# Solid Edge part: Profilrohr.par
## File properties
Username: bmolnar
Dokumentum tartalom típus: 0
Author: bmolnar
Last saved by: bmolnar
Revision: 91
Sűrűség: 0,000 kg/m^3
Pontosság: 0,990
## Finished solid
Body 1: solid body, 115 faces, 338 edges, 224 vertices.
  Faces by surface: cylinder 59, plane 56
  Edges by curve: line 220, circle 118
Bounding box of the edges (mm): 95.500 x 95.500 x 184.000, from (-47.75, -47.75, -155) to (47.75, 47.75, 29).
Cylindrical faces by radius (mm): R0.2 x24, R0.5 x24, R1 x4, R10 x4, R13.5 x2, R40 x1
Planar faces by outward normal: +x 13, +y 14, +z 1, -x 13, -y 14, -z 1
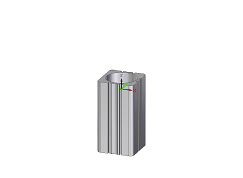
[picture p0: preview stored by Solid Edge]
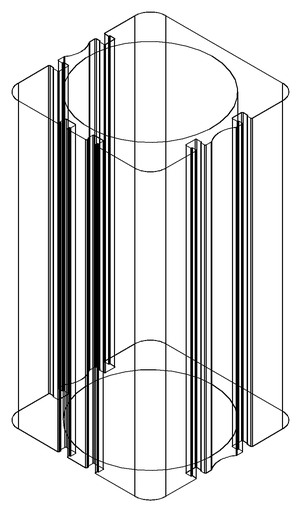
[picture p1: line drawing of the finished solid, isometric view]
